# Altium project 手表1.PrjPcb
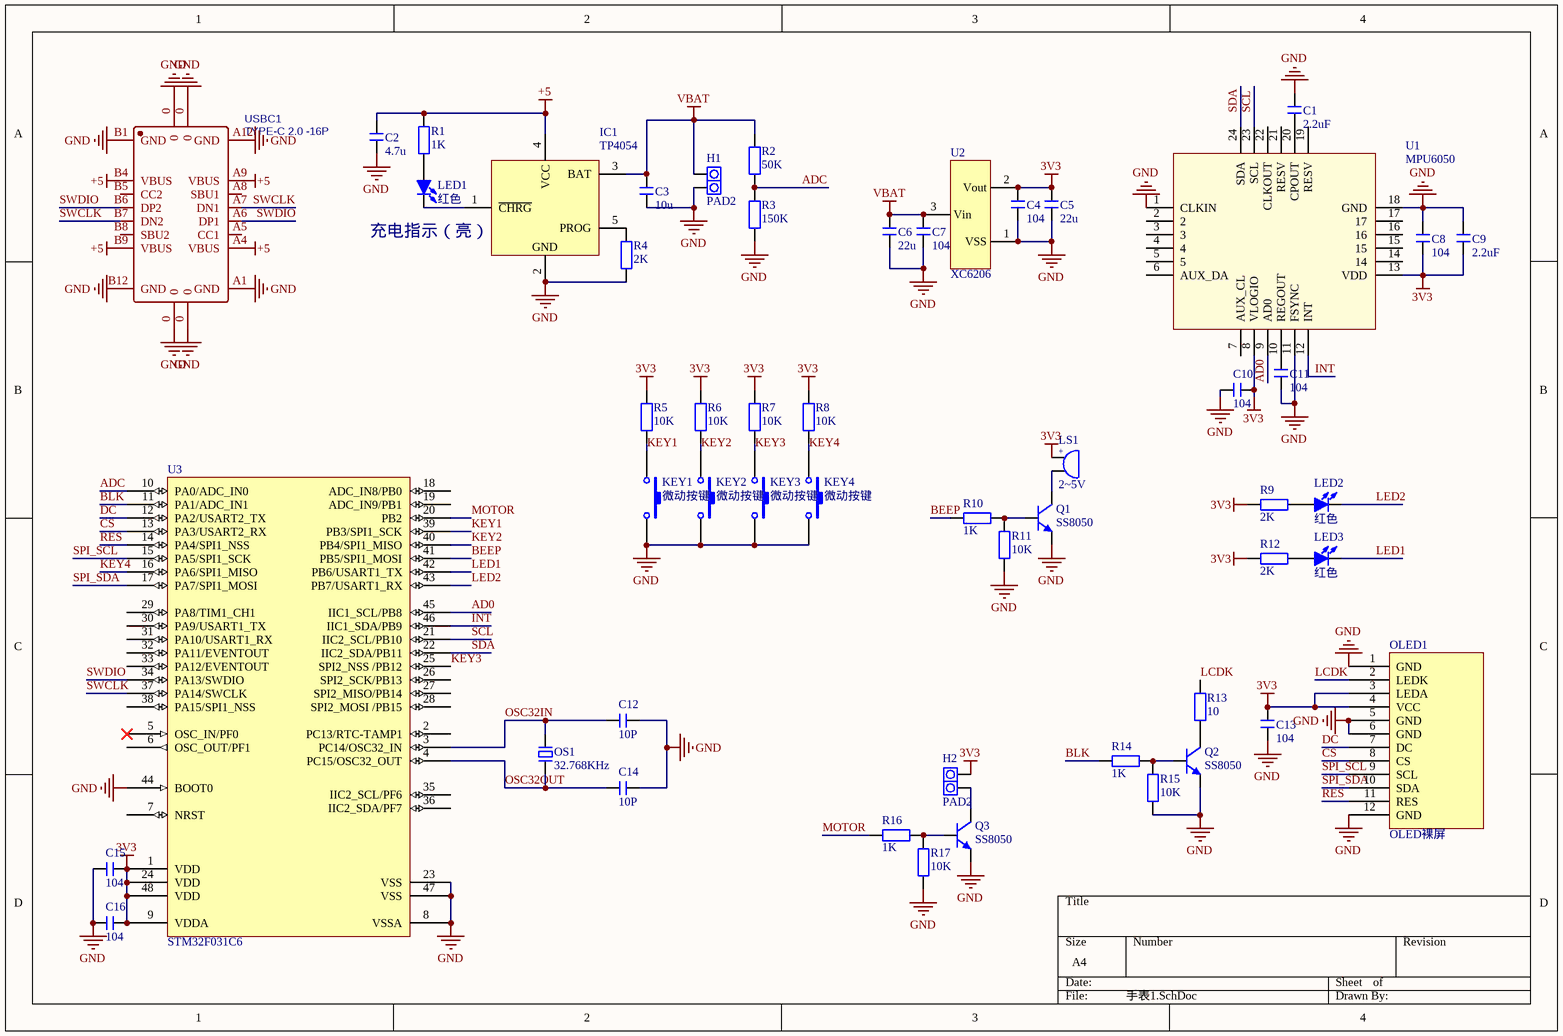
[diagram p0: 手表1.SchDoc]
1 sheet, 53 parts. Net scope: global (net labels, ports and power ports of the same name join across sheets).
Board file: 手表1.PcbDoc

## Sheet 手表1.SchDoc
size A4; SheetNumber: 1; SheetTotal: 1

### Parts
C1  2.2uF  [C 0603_L]
C2  4.7u  [C 0603_L]
C3  10u  [C 0603_L]
C4  104  [C 0603_L]
C5  22u  [C 0805_L]
C6  22u  [C 0805_L]
C7  104  [C 0603_L]
C8  104  [C 0603_L]
C9  2.2uF  [C 0603_L]
C10  104  [C 0603_L]
C11  104  [C 0603_L]
C12  10P  [C 0603_M]
C13  104  [C 0603_L]
C14  10P  [C 0603_M]
C15  104  [C 0603_L]
C16  104  [C 0603_L]
H1  PAD2  [PAD2-2.54]
H2  PAD2  [PAD2-2.54]
IC1  TP4054  [SOT-25]
KEY1  微动按键  [YD-3410小龟/微动开关]
KEY2  微动按键  [YD-3410小龟/微动开关]
KEY3  微动按键  [YD-3410小龟/微动开关]
KEY4  微动按键  [YD-3410小龟/微动开关]
LED1  红色  [LED 0603R]
LED2  红色  [LED 0603R]
LED3  红色  [LED 0603R]
LS1  2~5V  [BEEP SMD 5*5*2]
OLED1  OLED裸屏  [圆形IPS LCD屏]
OS1  32.768KHz  [OSC 3215-2P]
Q1  SS8050  [SOT23-3N]
Q2  SS8050  [SOT23-3N]
Q3  SS8050  [SOT23-3N]
R1  1K  [R 0603_L]
R2  50K  [R 0603_L]
R3  150K  [R 0603_L]
R4  2K  [R 0603_L]
R5  10K  [R 0603_L]
R6  10K  [R 0603_L]
R7  10K  [R 0603_L]
R8  10K  [R 0603_L]
R9  2K  [R 0603_L]
R10  1K  [R 0603_L]
R11  10K  [R 0603_L]
R12  2K  [R 0603_L]
R13  10  [R 0603_L]
R14  1K  [R 0603_L]
R15  10K  [R 0603_L]
R16  1K  [R 0603_L]
R17  10K  [R 0603_L]
U1  MPU6050  [QFN_24]
U2  XC6206  [SOT23-3L]
U3  STM32F031C6  [LQFP48 7X7_N]
USBC1  TYPE-C 2.0 -16P  [USB-C-SMD_TYPE-C-USB-5]

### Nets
3V3: C4.2 C5.2 C8.1 C9.1 C10.1 C13.1 C15.1 C16.1 H2.2 LS1.1 OLED1.3(LEDA) OLED1.4(VCC) R5.1 R6.1 R7.1 R8.1 R9.2 R12.2 U1.8(VLOGIO) U1.13(VDD) U2.2(Vout) U3.1(VDD) U3.9(VDDA) U3.24(VDD) U3.48(VDD)
+5: C2.2 IC1.4(VCC) R1.2 USBC1.A4(VBUS) USBC1.A9(VBUS) USBC1.B4(VBUS) USBC1.B9(VBUS)
GND: C1.1 C2.1 C3.1 C4.1 C5.1 C6.1 C7.1 C8.2 C9.2 C10.2 C11.1 C12.1 C13.2 C14.1 C15.2 C16.2 H1.2 IC1.2(GND) KEY1.2 KEY2.2 KEY3.2 KEY4.2 OLED1.1(GND) OLED1.5(GND) OLED1.6(GND) OLED1.12(GND) Q1.2(E) Q2.2(E) Q3.2(E) R3.1 R4.1 R11.2 R15.1 R17.2 U1.1(CLKIN) U1.11(FSYNC) U1.18(GND) U2.1(VSS) U3.8(VSSA) U3.23(VSS) U3.44(BOOT0) U3.47(VSS) USBC1.0 USBC1.A1(GND) USBC1.A12(GND) USBC1.B1(GND) USBC1.B12(GND)
VBAT: C3.2 C6.2 C7.2 H1.1 IC1.3(BAT) R2.2 U2.3(Vin)
AD0: U1.9(AD0) U3.45(IIC1_SCL/PB8)
ADC: R2.1 R3.2 U3.10(PA0/ADC_IN0)
BEEP: R10.1 U3.41(PB5/SPI1_MOSI)
BLK: R14.1 U3.11(PA1/ADC_IN1)
CS: OLED1.8(CS) U3.13(PA3/USART2_RX)
DC: OLED1.7(DC) U3.12(PA2/USART2_TX)
INT: U1.12(INT) U3.46(IIC1_SDA/PB9)
KEY1: KEY1.1 R5.2 U3.39(PB3/SPI1_SCK)
KEY2: KEY2.1 R6.2 U3.40(PB4/SPI1_MISO)
KEY3: KEY3.1 R7.2 U3.25(SPI2_NSS_/PB12)
KEY4: KEY4.1 R8.2 U3.16(PA6/SPI1_MISO)
LCDK: OLED1.2(LEDK) R13.2
LED1: LED3.2(K) U3.42(PB6/USART1_TX)
LED2: LED2.2(K) U3.43(PB7/USART1_RX)
MOTOR: R16.1 U3.20(PB2)
OSC32IN: C12.2 OS1.2 U3.3(PC14/OSC32_IN)
OSC32OUT: C14.2 OS1.1 U3.4(PC15/OSC32_OUT)
RES: OLED1.11(RES) U3.14(PA4/SPI1_NSS)
SCL: U1.23(SCL) U3.21(IIC2_SCL/PB10)
SDA: U1.24(SDA) U3.22(IIC2_SDA/PB11)
SPI_SCL: OLED1.9(SCL) U3.15(PA5/SPI1_SCK)
SPI_SDA: OLED1.10(SDA) U3.17(PA7/SPI1_MOSI)
SWCLK: U3.37(PA14/SWCLK) USBC1.A7(DN1) USBC1.B7(DN2)
SWDIO: U3.34(PA13/SWDIO) USBC1.A6(DP1) USBC1.B6(DP2)
NetC1_2: C1.2 U1.20(CPOUT)
NetC11_2: C11.2 U1.10(REGOUT)
NetH2_1: H2.1 Q3.3(C)
NetIC1_1: IC1.1(~{CHRG}) LED1.2(K)
NetIC1_5: IC1.5(PROG) R4.2
NetLED1_1: LED1.1(A) R1.1
NetLED2_1: LED2.1(A) R9.1
NetLED3_1: LED3.1(A) R12.1
NetLS1_3: LS1.3 Q1.3(C)
NetQ1_1: Q1.1(B) R10.2 R11.1
NetQ2_1: Q2.1(B) R14.2 R15.2
NetQ2_3: Q2.3(C) R13.1
NetQ3_1: Q3.1(B) R16.2 R17.1

Not connected (* = marked no-connect by the designer): U1 2 3 4 5 6(AUX_DA) 7(AUX_CL) 14 15 16 17 19(RESV) 21(RESV) 22(CLKOUT); U3 2(PC13/RTC-TAMP1) 5(OSC_IN/PF0)* 6(OSC_OUT/PF1) 7(NRST) 18(ADC_IN8/PB0) 19(ADC_IN9/PB1) 26(SPI2_SCK/PB13) 27(SPI2_MISO/PB14) 28(SPI2_MOSI_/PB15) 29(PA8/TIM1_CH1) 30(PA9/USART1_TX) 31(PA10/USART1_RX) 32(PA11/EVENTOUT) 33(PA12/EVENTOUT) 35(IIC2_SCL/PF6) 36(IIC2_SDA/PF7) 38(PA15/SPI1_NSS); USBC1 A5(CC1) A8(SBU1) B5(CC2) B8(SBU2)

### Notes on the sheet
- (near LED1) 充电指示（亮）

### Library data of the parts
C1-C16 = C: 贴片电容; BOM名称: 无极性贴片电容; 淘宝ID: 封装库来自淘宝 ID：黄晶宝石
H1 H2 = PAD2: 引线焊盘; 版权归属: 封装库来自淘宝 ID：黄晶宝石
IC1 = TP4054: 锂电池充电管理; 淘宝ID: 封装库来自淘宝 ID：黄晶宝石
KEY1-KEY4 = YD-3410小龟: YD-3410小龟侧躺
LED1-LED3 = LED-SMD: 贴片LED; 版权归属: 封装库来自淘宝 ID：黄晶宝石
LS1 = BEEP_SMD: 贴片无源蜂鸣器
OLED1 = 圆形IPS LCD屏
OS1 = XTAL-2P: 2脚无源脚晶振; 版权归属: 封装库来自淘宝卖家 ID：黄晶宝石
Q1-Q3 = 8050-SMD: 高频放大-NPN型; 版权归属: 封装库来自淘宝 ID：黄晶宝石; 属性: 40V 1.5A 1W 100MHZ
R1-R17 = R: 贴片电阻; 版权归属: 来自淘宝 ID：黄晶宝石; 封装库来自淘宝卖家 ID：黄晶宝石: 其他店铺购入均为盗版，不享受售后技术支持服务，请立即申请退款
U1 = MPU6050: 三轴加速度+三轴陀螺仪; 淘宝ID:黄晶宝石: 封装库来自淘宝卖家 ID：黄晶宝石; 封装库来自淘宝卖家 ID：黄晶宝石: 其他店铺购入均为盗版，不享受售后技术支持服务，请立即申请退款
U2 = XC6206: 小体积线性稳压器
U3 = STM32F030C6: 32位STM单片机; 版权归属: 源创客
USBC1 = USB2.0 Type-C 16Pin母座: USB2.0 Type-C 母座 16Pin; BOM_Manufacturer: LCSC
